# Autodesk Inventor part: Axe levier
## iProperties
Author: Flavien MARTY
Shininess: 86.0
PropertySet Name: _Private Model Information
Created: 2001-10
Part Number: Axe levier
Material: Par défaut
Document SubType Name: Modélisation
Designer: Flavien MARTY
Control State: 0
Master: False
Checked Out: False
PropertySet Name: Design Tracking Control
Density: 0.0
Volumn: 0.0
Area: 0.0
PropertySet Name: Model Information
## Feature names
1. Base1
